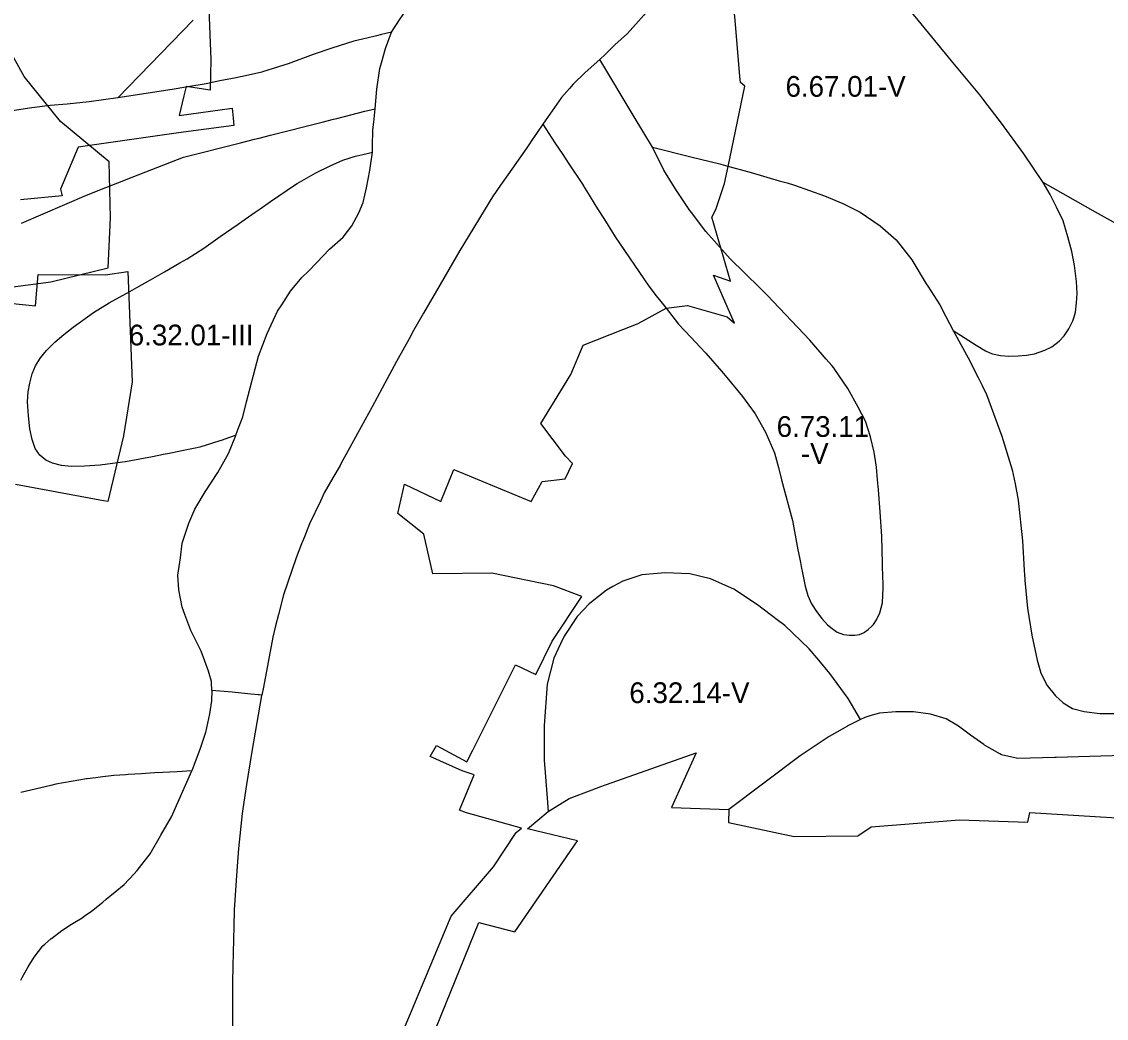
# Model space of a CAD drawing. Extents: x -555156 to -540209, y -1046851 to -1035695.
# Drawn here: x -542661 to -542138, y -1039446 to -1038966 of the extents above; entities that cross this region are included whole.
import ezdxf

# ---------------------------------------------------------------- set-up
doc = ezdxf.new("R2010")
doc.units = 0
for name, color, linetype in [('Vrstva 12', 7, 'Continuous'), ('Vrstva 27', 7, 'Continuous'), ('Vrstva 28', 7, 'Continuous'), ('Vrstva 29', 7, 'Continuous')]:
    doc.layers.add(name, color=color, linetype=linetype)

msp = doc.modelspace()

# ---------------------------------------------------------------- linework, layer by layer
at = {"layer": 'Vrstva 12'}
for points in [[(-542571.16, -1038959.76), (-542570.2, -1038984.03), (-542570.42864, -1038998.843094), (-542582.08, -1038997.13), (-542583.15, -1039001.54), (-542585.45, -1039011.04), (-542559.91, -1039007.59), (-542559.38, -1039012.36), (-542559.041327, -1039015.905199), (-542585.8, -1039019.36), (-542634.112961, -1039026.305601), (-542642.72, -1039046.62), (-542641.9, -1039049.84), (-542661.98, -1039051.71)], [(-542478.96, -1039456.24), (-542473.9, -1039444.11), (-542454.3, -1039397.07), (-542433.82, -1039373.33), (-542422.83, -1039356.84), (-542420.35, -1039354.71), (-542446.86, -1039347.35), (-542450.258345, -1039346.01536), (-542443.11, -1039329), (-542448.89, -1039327.04), (-542464.421409, -1039320.096229), (-542461.38, -1039314.75), (-542446.719551, -1039322.724992), (-542443.86, -1039317.04), (-542442.71, -1039314.76), (-542423.21, -1039275.98), (-542413.43, -1039280.57), (-542405.54, -1039264.51), (-542391.281956, -1039243.045785), (-542404.87, -1039237.88), (-542434.66, -1039231.8), (-542463.06, -1039232.08), (-542467.37, -1039212.86), (-542480.04, -1039203), (-542476.72, -1039188.86), (-542459.17, -1039197.15), (-542452.91, -1039181.69), (-542415.621243, -1039197.145894), (-542410.31, -1039187.58), (-542399.245129, -1039186.292847), (-542395.69, -1039178.86), (-542399.06, -1039175.35), (-542410.98, -1039159.52), (-542396.61, -1039135.93), (-542390.54, -1039121.83), (-542371.5, -1039114.28), (-542364.06, -1039111.33), (-542350.54, -1039104), (-542340.27, -1039102.6), (-542321.08, -1039108.2), (-542317.64, -1039111.15), (-542320.6, -1039104.35), (-542327.73, -1039087.99), (-542319.48, -1039090.9), (-542328.508146, -1039060.120593), (-542326.56, -1039056.44), (-542322.46, -1039043.93), (-542320.72, -1039035.68), (-542312.56, -1038996.85), (-542314.71, -1038995.19), (-542314.95, -1038992.34), (-542317.12, -1038966.99), (-542317.7, -1038960.14)], [(-542665.61, -1039101.66), (-542654.7, -1039102.81), (-542653.48, -1039087.68), (-542620.98, -1039087.89), (-542610.19, -1039086.31), (-542608.17, -1039139.45), (-542612.35, -1039165.58), (-542619.81, -1039197.17), (-542621.94, -1039196.81), (-542664.31, -1039188.99)]]:
    msp.add_lwpolyline(points, dxfattribs=at)
at = {"layer": 'Vrstva 28'}
for points in [[(-542483.1, -1038970.94), (-542479.17, -1038964.93), (-542477.35, -1038962.4), (-542474.47, -1038958.39), (-542468.95, -1038952.18), (-542468.2, -1038951.33), (-542462.37, -1038944.66), (-542462.3, -1038944.58), (-542462.2, -1038944.46), (-542454.69, -1038936.08), (-542443.9, -1038924.06), (-542431.62, -1038909.42), (-542425.01, -1038900.53), (-542422.47, -1038897.12), (-542415.67, -1038885.35), (-542414.79, -1038883.26), (-542412.3, -1038877.34), (-542409.4, -1038870.45), (-542408.17, -1038866.94), (-542405.82, -1038860.21), (-542405.07, -1038858.06), (-542402.72, -1038851.35)], [(-542330.33, -1038913.06), (-542332.56, -1038917.03), (-542341.34, -1038932.65), (-542343.36, -1038936.25), (-542349.37, -1038946.45), (-542355.12, -1038955.08), (-542359.2, -1038960.01), (-542361.4, -1038962.67), (-542369.24, -1038971.56), (-542375.25, -1038977.05), (-542377.53, -1038979.23), (-542379.82, -1038981.42), (-542382.61, -1038984.08)], [(-542168.66, -1039043.38), (-542178.1, -1039029.62), (-542188.82, -1039014.72), (-542195.26, -1039006.35), (-542197.77, -1039003.09), (-542199.28, -1039001.12), (-542212.87, -1038984.64), (-542229.08, -1038965.03), (-542255.93, -1038932.48)], [(-542615.06, -1039002.55), (-542578.66, -1038965.04)], [(-542483.1, -1038970.94), (-542487.85, -1038972.05), (-542490.34, -1038972.63), (-542491.48, -1038972.9), (-542497.05, -1038974.28), (-542501.12, -1038975.29), (-542508.32, -1038977.46), (-542511.88, -1038978.53), (-542520.84, -1038981.67), (-542532.94, -1038986.15), (-542534.41, -1038986.62), (-542538.06, -1038987.78), (-542545.19, -1038990.04), (-542545.57, -1038990.13), (-542554.9, -1038992.28), (-542555.82, -1038992.46), (-542558.02, -1038992.89), (-542565.77, -1038994.42), (-542572.37, -1038995.72), (-542581.27, -1038997.26), (-542582.15, -1038997.41), (-542588.8, -1038998.56)], [(-542490.94, -1039007.82), (-542490.15, -1038998.4), (-542488.58, -1038988.47), (-542487.81, -1038985.63), (-542485.97, -1038978.79), (-542483.1, -1038970.94)], [(-542382.61, -1038984.08), (-542389.63, -1038990.35), (-542395.45, -1038995.88), (-542397.23, -1038997.99), (-542400.98, -1039002.46), (-542405.46, -1039008.88), (-542410.09, -1039015.31)], [(-542357.19, -1039026.31), (-542365.96, -1039011.74), (-542382.61, -1038984.08)], [(-542588.8, -1038998.56), (-542615.06, -1039002.55)], [(-542615.06, -1039002.55), (-542628.9, -1039004.45), (-542639.51, -1039005.64), (-542647.72, -1039006.24), (-542656.54, -1039007.44), (-542665.91, -1039008.89), (-542676.07, -1039010.69), (-542686.37, -1039012.63), (-542700.12, -1039016.07), (-542712.51, -1039019.95), (-542720.49, -1039023.11), (-542724.61, -1039024.74), (-542737.76, -1039031.91), (-542752.54, -1039040.58), (-542760.09, -1039045.96)], [(-542661.43, -1039062.91), (-542640.66, -1039053.96), (-542630.18, -1039049.45), (-542626.36, -1039047.96), (-542623.7, -1039046.92), (-542612.15, -1039042.4), (-542611.03, -1039041.96), (-542583.39, -1039031.14), (-542555.81, -1039024.19), (-542549.16, -1039022.51), (-542546.87, -1039021.93), (-542541.38, -1039020.54), (-542516.43, -1039014.25), (-542510.98, -1039012.88), (-542509.42, -1039012.49), (-542495.82, -1039009.05), (-542490.94, -1039007.82)], [(-542492.24, -1039028.74), (-542492.17, -1039026.06), (-542491.98, -1039018.02), (-542491.61, -1039014.35), (-542490.94, -1039007.82)], [(-542410.09, -1039015.31), (-542413.09, -1039019.71), (-542415.01, -1039022.53), (-542417.11, -1039025.62), (-542417.81, -1039026.63), (-542425.03, -1039036.98), (-542431.57, -1039046.27), (-542433.21, -1039048.61), (-542433.84, -1039049.5), (-542450.05, -1039076.17), (-542461.33, -1039095.67), (-542467.54, -1039106.4), (-542473.05, -1039115.93), (-542473.78, -1039117.26), (-542480.57, -1039129.73), (-542485.14, -1039138.11), (-542492.41, -1039151.46), (-542499.46, -1039164.4), (-542504.11, -1039172.94), (-542507.29, -1039178.77), (-542507.82, -1039179.74), (-542511.27, -1039185.71), (-542515.48, -1039193), (-542517.35, -1039196.94), (-542522.54, -1039207.91), (-542525.01, -1039214.14), (-542526.36, -1039217.55), (-542529.07, -1039224.38), (-542535.08, -1039242.17), (-542537.52, -1039251.7), (-542538.93, -1039257.19), (-542540.31, -1039262.57), (-542544.81, -1039286.67), (-542545.54, -1039290.55)], [(-542410.09, -1039015.31), (-542404.21, -1039024.18), (-542400.47, -1039029.84), (-542397.83, -1039033.82), (-542390.6, -1039044.72), (-542390.56, -1039044.79), (-542388.96, -1039047.36), (-542383.6, -1039055.99), (-542380.67, -1039060.71), (-542375.7, -1039068.73), (-542375.18, -1039069.56), (-542358.98, -1039093.36), (-542355.32, -1039098.01), (-542353.15, -1039100.77), (-542350.59, -1039104.02), (-542344.53, -1039111.73), (-542338.7, -1039117.91), (-542334.2, -1039122.69), (-542331.46, -1039125.6), (-542323.89, -1039134.33), (-542321.27, -1039137.36), (-542313.69, -1039146.52), (-542307.68, -1039154.89), (-542302.71, -1039163.78), (-542298.27, -1039173.72), (-542296.43, -1039180.79), (-542294.87, -1039186.79), (-542289.64, -1039206.41), (-542287.03, -1039220.53), (-542286.3, -1039224.15), (-542285.83, -1039226.51), (-542285.42, -1039228.57)], [(-542631.04, -1039180.21), (-542637.44, -1039180.29), (-542642.13, -1039179.78), (-542646.49, -1039178.76), (-542649.82, -1039177.31), (-542652.63, -1039174.91), (-542654.85, -1039171.66), (-542656.39, -1039167.22), (-542657.41, -1039162.1), (-542658.18, -1039155.95), (-542658.52, -1039149.12), (-542658.27, -1039144.25), (-542657.5, -1039140.15), (-542656.3, -1039135.62), (-542654.77, -1039131.78), (-542652.29, -1039127.85), (-542649.47, -1039124.44), (-542645.46, -1039120.34), (-542641.02, -1039116.58), (-542636.63, -1039113.14), (-542626.77, -1039106.11), (-542619.15, -1039101.33), (-542609.31, -1039095.91), (-542605.86, -1039094.01), (-542599.32, -1039090.27), (-542592.56, -1039086.39), (-542585.08, -1039082.08), (-542581.66, -1039080.11), (-542573.57, -1039075.04), (-542565.59, -1039069.46), (-542556.95, -1039063.43), (-542555.19, -1039062.2), (-542548.71, -1039057.67), (-542546.83, -1039056.36), (-542546.32, -1039056.01), (-542541.32, -1039052.59), (-542529.35, -1039044.4), (-542528.53, -1039043.93), (-542519.49, -1039038.72), (-542512.62, -1039035.28), (-542506.5, -1039032.59), (-542503.39, -1039031.6), (-542502.07, -1039031.18), (-542500.37, -1039030.65), (-542494.69, -1039029.32), (-542492.24, -1039028.74)], [(-542558.11, -1039165.22), (-542557.4, -1039163.38), (-542556.96, -1039162.19), (-542554.78, -1039156.32), (-542552.89, -1039149.1), (-542550.34, -1039139.32), (-542547.2, -1039127.03), (-542542.94, -1039116.1), (-542537.97, -1039105.37), (-542536, -1039102.34), (-542531.7, -1039095.7), (-542526.21, -1039089.16), (-542522.94, -1039085.89), (-542519.15, -1039082.1), (-542512.88, -1039075.56), (-542506.34, -1039069.8), (-542502.16, -1039064.31), (-542498.76, -1039058.03), (-542496.67, -1039053.07), (-542495.1, -1039046), (-542493.55, -1039037.63), (-542492.24, -1039028.74)], [(-542259.63, -1039261.69), (-542257.32, -1039261.26), (-542255.02, -1039260.32), (-542254.82, -1039260.17), (-542253.14, -1039258.95), (-542251.33, -1039257.26), (-542250.58, -1039256.56), (-542249.05, -1039254.26), (-542247.51, -1039250.84), (-542246.23, -1039246.06), (-542245.89, -1039238.8), (-542246.1, -1039231.4), (-542246.14, -1039230.05), (-542246.16, -1039229.26), (-542246.22, -1039227.01), (-542246.58, -1039214), (-542247.32, -1039202.19), (-542248.22, -1039191.58), (-542248.61, -1039186.8), (-542249.12, -1039180.67), (-542250.27, -1039173.31), (-542251.92, -1039165.99), (-542254.46, -1039158.52), (-542257.89, -1039151.64), (-542262.97, -1039142.68), (-542269.13, -1039133.49), (-542269.69, -1039132.66), (-542270.67, -1039131.53), (-542273.31, -1039128.47), (-542281.19, -1039119.33), (-542301.81, -1039097.66), (-542305.39, -1039094.17), (-542319.73, -1039080.18), (-542327.48, -1039071.47), (-542331.5, -1039066.96), (-542335.49, -1039061.63), (-542338.17, -1039058.06), (-542339.12, -1039056.8), (-542345.84, -1039046.78), (-542351.67, -1039037.37), (-542357.19, -1039026.31)], [(-542357.19, -1039026.31), (-542338.63, -1039030.94), (-542324.65, -1039034.43), (-542322.62, -1039034.99), (-542309.49, -1039038.61), (-542296.01, -1039042.49), (-542292.15, -1039043.6), (-542288.58, -1039044.63), (-542274.2, -1039049.86), (-542265.32, -1039053.52), (-542256.95, -1039057.71), (-542247.28, -1039064.24), (-542239.7, -1039071.04), (-542232.12, -1039080.72), (-542225.13, -1039092.23), (-542224.42, -1039093.34), (-542220.07, -1039100.12), (-542218.59, -1039102.43), (-542215.63, -1039108.01), (-542212.06, -1039114.72)], [(-542212.06, -1039114.72), (-542201.02, -1039121.73), (-542196.49, -1039124.55), (-542194.42, -1039125.45), (-542193.16, -1039126), (-542189.24, -1039126.85), (-542185.31, -1039127.11), (-542180.7, -1039127.02), (-542176.77, -1039126.59), (-542172.85, -1039125.91), (-542167.9, -1039124.29), (-542164.57, -1039122.58), (-542160.98, -1039119.93), (-542158.59, -1039117.37), (-542156.29, -1039113.87), (-542154.41, -1039110.11), (-542153.8, -1039108.12), (-542153.13, -1039105.93), (-542152.62, -1039101.32), (-542152.28, -1039096.96), (-542152.62, -1039091.15), (-542153.57, -1039083.44), (-542154.91, -1039076.56), (-542156.86, -1039069.54), (-542159.1, -1039061.92), (-542162.23, -1039055.34), (-542165.37, -1039049.21), (-542168.66, -1039043.38)], [(-541966.55, -1039120.89), (-541975.81, -1039111.77), (-541985.07, -1039105.65), (-541993.44, -1039100.86), (-542005.09, -1039096.68), (-542005.7, -1039096.5), (-542009.49, -1039095.4), (-542013.31, -1039094.29), (-542022.87, -1039092.94), (-542034.07, -1039091.9), (-542046.65, -1039090.03), (-542059.35, -1039087.79), (-542075.03, -1039084.95), (-542085.49, -1039082.56), (-542095.79, -1039079.57), (-542107.59, -1039075.68), (-542120.44, -1039070.15), (-542131.94, -1039064.17), (-542143.44, -1039057.75), (-542168.66, -1039043.38)], [(-542212.06, -1039114.72), (-542203.95, -1039129.63), (-542202.11, -1039133.37), (-542200.14, -1039137.38), (-542198.2, -1039141.32), (-542196.11, -1039145.58), (-542188.6, -1039165.66), (-542183.63, -1039181.87), (-542182.29, -1039188.67), (-542180.75, -1039196.52), (-542178.66, -1039216.13), (-542177.84, -1039230.34), (-542177.72, -1039232.51), (-542177.59, -1039234.68), (-542177.55, -1039235.29), (-542176.25, -1039248.63), (-542174.15, -1039261.7), (-542171.54, -1039273.74), (-542170.33, -1039278.15), (-542169.86, -1039279.87), (-542166.72, -1039285.85), (-542162.84, -1039290.93), (-542159.11, -1039294.22), (-542154.62, -1039296.91), (-542148.95, -1039298.4), (-542141.33, -1039299.45), (-542134.01, -1039299.45)], [(-542558.11, -1039165.22), (-542558.41, -1039165.33), (-542563.39, -1039167.1), (-542564.68, -1039167.53), (-542568.47, -1039168.79), (-542569.8, -1039169.24), (-542575.02, -1039170.81), (-542575.43, -1039170.94), (-542577.76, -1039171.45), (-542583.28, -1039172.65), (-542588.61, -1039173.7), (-542590.99, -1039174.17), (-542592.17, -1039174.4), (-542599.12, -1039175.77), (-542601.83, -1039176.26), (-542611.32, -1039177.99), (-542611.51, -1039178.02), (-542615.22, -1039178.54), (-542623.53, -1039179.7), (-542631.04, -1039180.21)], [(-542569.64, -1039288.23), (-542569.79, -1039284.49), (-542569.92, -1039284.01), (-542570.96, -1039280.05), (-542571.33, -1039279.05), (-542574.88, -1039269.32), (-542579.84, -1039259.38), (-542582.74, -1039251.6), (-542584.03, -1039248.14), (-542585.59, -1039239.77), (-542586.05, -1039232.74), (-542584.75, -1039224.37), (-542583.96, -1039217.31), (-542580.82, -1039207.63), (-542577.81, -1039200.9), (-542577.43, -1039200.05), (-542572.98, -1039192.46), (-542566.81, -1039183.26), (-542561.58, -1039174.11), (-542558.14, -1039165.3), (-542558.11, -1039165.22)], [(-542285.42, -1039228.57), (-542284.67, -1039232.3), (-542283.44, -1039237.94), (-542282.16, -1039242.47), (-542280.46, -1039246.48), (-542277.98, -1039250.24), (-542275.5, -1039253.57), (-542272.77, -1039256.65), (-542270.47, -1039258.44), (-542268.08, -1039260.15), (-542265.09, -1039261.34), (-542262.19, -1039261.69), (-542259.63, -1039261.69)], [(-542256.86, -1039302.32), (-542262.74, -1039292.16), (-542271.55, -1039280.06), (-542276.98, -1039273.65), (-542281.56, -1039268.25), (-542293.36, -1039257.04), (-542296.95, -1039254.31), (-542306.5, -1039247.03), (-542317.85, -1039239.41), (-542329.2, -1039234.48), (-542339.06, -1039232.08), (-542351.01, -1039231.64), (-542362.21, -1039232.53), (-542371.48, -1039235.52), (-542376.26, -1039238.23), (-542379.39, -1039240), (-542387.1, -1039246.06), (-542387.76, -1039246.58), (-542390.46, -1039249.42), (-542393.51, -1039252.63), (-542399.78, -1039262.05), (-542401.53, -1039265.82), (-542404.75, -1039272.77), (-542407.88, -1039285.33), (-542409.45, -1039305.2), (-542409.45, -1039321.94), (-542408.98, -1039327.9), (-542407.83, -1039342.38), (-542407.49, -1039346.72)], [(-542569.64, -1039288.23), (-542569.79, -1039293.31), (-542570.84, -1039299.59), (-542572.78, -1039308.55), (-542575.32, -1039316.33), (-542579.35, -1039327.09)], [(-542545.54, -1039290.55), (-542546.85, -1039290.42), (-542547.26, -1039290.38), (-542552.34, -1039289.9), (-542559.81, -1039289.18), (-542569.64, -1039288.23)], [(-542559.32, -1039476.62), (-542559.51, -1039441.98), (-542559.57, -1039431.43), (-542559.58, -1039428.76), (-542559.41, -1039421.25), (-542558.98, -1039401.86), (-542558.8, -1039393.98), (-542557.47, -1039375.21), (-542556.71, -1039364.42), (-542554.87, -1039347.66), (-542554.61, -1039345.33), (-542552.78, -1039333.61), (-542551.22, -1039323.62), (-542550.86, -1039321.51), (-542549.39, -1039312.99), (-542545.57, -1039290.71), (-542545.54, -1039290.55)], [(-542256.86, -1039302.32), (-542257.15, -1039302.47), (-542262.59, -1039305.18), (-542263.1, -1039305.46), (-542272, -1039310.41)], [(-542188.88, -1039319.3), (-542189.66, -1039318.85), (-542196.98, -1039314.6), (-542197.41, -1039314.3), (-542203.78, -1039309.89), (-542209.53, -1039305.44), (-542215.54, -1039302.04), (-542223.12, -1039299.69), (-542231.23, -1039298.64), (-542239.85, -1039298.64), (-542247.69, -1039299.17), (-542252.4, -1039300.57), (-542254.75, -1039301.26), (-542256.86, -1039302.32)], [(-542272, -1039310.41), (-542285.86, -1039319.83), (-542320.39, -1039345.74)], [(-542407.49, -1039346.72), (-542397.39, -1039340.33), (-542386.23, -1039336.15), (-542382.08, -1039334.6), (-542336.03, -1039318.43), (-542347.98, -1039344.66), (-542320.39, -1039345.74)], [(-542124.74, -1039319.46), (-542162.43, -1039320.65), (-542163.11, -1039320.67), (-542180.95, -1039321.13), (-542188.88, -1039319.3)], [(-542661.79, -1039427.89), (-542661.17, -1039426.74), (-542658.35, -1039421.47), (-542655.36, -1039416.83), (-542651.18, -1039411.45), (-542650.25, -1039410.62), (-542648.82, -1039409.35), (-542647.15, -1039407.87), (-542647.09, -1039407.82), (-542642.07, -1039403.98), (-542638.34, -1039401.59), (-542638.2, -1039401.51), (-542635.71, -1039399.99), (-542632.21, -1039397.85), (-542631.24, -1039397.18), (-542627.69, -1039394.72), (-542622.31, -1039390.32), (-542620.64, -1039388.96), (-542612.01, -1039381.9), (-542607.29, -1039376.78), (-542605.74, -1039375.1), (-542599.46, -1039366.99), (-542594.37, -1039358.33), (-542594.23, -1039358.1), (-542589.17, -1039349.24), (-542579.35, -1039327.09)], [(-542579.35, -1039327.09), (-542586.35, -1039327.47), (-542593.51, -1039327.85), (-542597.11, -1039328.05), (-542601.61, -1039328.29), (-542603.68, -1039328.43), (-542610, -1039328.86), (-542611.13, -1039328.94), (-542617.03, -1039329.34), (-542623.55, -1039330.14), (-542625.57, -1039330.39), (-542629.84, -1039330.91), (-542630.16, -1039330.97), (-542645, -1039333.52), (-542647.3, -1039334.06), (-542661.73, -1039337.44)], [(-542463.78, -1039456.45), (-542440.83, -1039400.18), (-542423.47, -1039404.72), (-542393.35, -1039360.84), (-542417.42, -1039354.96), (-542407.49, -1039346.72)], [(-542320.39, -1039345.74), (-542320.44, -1039351.97)], [(-542320.44, -1039351.97), (-542288.78, -1039358.76), (-542258.05, -1039358.37), (-542251.72, -1039353.97), (-542209.02, -1039350.73), (-542176.16, -1039351.76), (-542175.22, -1039347.18), (-542080.59, -1039352.93)]]:
    msp.add_lwpolyline(points, dxfattribs=at)
at = {"layer": 'Vrstva 29'}
msp.add_lwpolyline([(-542682.703007, -1039095.925008), (-542647.328001, -1039091.194996), (-542619.657007, -1039084.525006), (-542618.575003, -1039060.365996), (-542619.212005, -1039033.445999), (-542642.753998, -1039014.020997), (-542660.130994, -1038992.262992), (-542673.644997, -1038968.154008)], dxfattribs=at)

# ---------------------------------------------------------------- texts
at = {"layer": 'Vrstva 27'}
for s, p in [('6.67.01-V', (-542292.981006, -1039002.02)), ('6.32.01-III', (-542609.756548, -1039121.91)), ('6.73.11', (-542297.263394, -1039166.02)), ('-V', (-542285.567227, -1039179.02)), ('6.32.14-V', (-542368.320884, -1039294.37))]:
    msp.add_text(s, height=10, dxfattribs=at).set_placement(p)

doc.saveas('drawing.dxf')
